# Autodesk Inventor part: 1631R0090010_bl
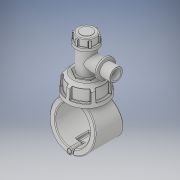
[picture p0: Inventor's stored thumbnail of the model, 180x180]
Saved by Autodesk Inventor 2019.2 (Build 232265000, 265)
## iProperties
Created: 2022-02
Part Number: 1631R0090010_bl
Material: Generic
Description: Plassadle Tapper Male 90x1''
Document SubType Name: Modeling
Designer: comp2
Density: 1 g/cm^3
Appearance: Default
Author: comp2
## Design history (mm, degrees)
derived "1631R.ipt"
feature "Solid1::1631R.ipt" dims "ScaleForDerivedMember" = 10
feature "Solid2::1631R.ipt" dims "ScaleForDerivedMember" = 10
feature "Solid3::1631R.ipt" dims "ScaleForDerivedMember" = 10
feature "Solid4::1631R.ipt" dims "ScaleForDerivedMember" = 10
tag "TaggingFeature1"
body "Solid1"
body "Solid2"
body "Solid3"
body "Solid4"
other parameters: "d2" = 119 [user parameter], "d3" = 45 [user parameter], "d5" = 258 [user parameter], "d7" = 113.05 [user parameter], "d8" = 85 deg [user parameter], "d9" = 45 deg [user parameter], "d10" = 102 [user parameter], "d11" = 49 [user parameter], "d12" = 34.3 [user parameter], "d13" = 42.84 [user parameter], "d14" = 57.936 [user parameter], "d15" = 2.45 [user parameter], "d16" = 2 [user parameter], "d17" = 2 [user parameter], "d18" = 29.4 [user parameter], "d19" = 7.35 [user parameter], "d20" = 1 [user parameter], "d21" = 30.6 [user parameter], "d22" = 1 [user parameter], "d23" = 14.7 [user parameter], "d24" = 78 [user parameter], "d27" = 144 [user parameter], "d29" = 49.8735 [user parameter], "d31" = 33.249 [user parameter], "d32" = 31.2 [user parameter], "d33" = 26.52 [user parameter], "d41" = 5 [user parameter], "d42" = 2.9 [user parameter], "d46" = 56.1 [user parameter], "d47" = 36.5739 [user parameter], "d48" = 49 [user parameter], "d49" = 2.38 [user parameter], "d50" = 94 [user parameter], "d51" = 0 [user parameter], "d52" = 20.3 [user parameter], "d53" = 65.45 [user parameter], "d54" = 32.9 [user parameter], "d55" = 0 [user parameter], "d56" = 18.8 [user parameter], "d57" = 18.8 [user parameter], "d59" = 0 [user parameter], "d60" = 94 [user parameter], "d61" = 0 [user parameter], "d62" = 32.9 [user parameter], "d63" = 0 [user parameter], "d65" = 0 [user parameter], "d67" = 0 [user parameter], "d69" = 0 [user parameter], "d70" = 1 [user parameter], "d71" = 90.24 [user parameter], "d72" = 0 [user parameter], "d73" = 2 [user parameter], "d77" = 24.93675 [user parameter], "d78" = 86.7 [user parameter], "d79" = 5.1 [user parameter], "d80" = 60 deg [user parameter], "d81" = 5.1 [user parameter], "d84" = 0 [user parameter], "d85" = 1 [user parameter], "d87" = 360 deg [user parameter], "d90" = 0 [user parameter], "d91" = 1 [user parameter], "d93" = 60 deg [user parameter], "d94" = 3.06 [user parameter], "d95" = 3.06 [user parameter], "d97" = 0 [user parameter], "d98" = 0.5 [user parameter], "d100" = 360 deg [user parameter], "d102" = 2 [user parameter], "d117" = 0.5 [user parameter], "d118" = 31.2 [user parameter], "d119" = 100 deg [user parameter], "d121" = 0 [user parameter], "d1" = 25 [user parameter], "B" = 119 [user parameter], "L" = 94 [user parameter], "E_" = 54 [user parameter], "E1" = 102 [user parameter], "H1" = 258 [user parameter], "H2" = 144 [user parameter], "H3" = 78 [user parameter], "H_costum" = 49 [user parameter], "R" = 33.249 [user parameter]
